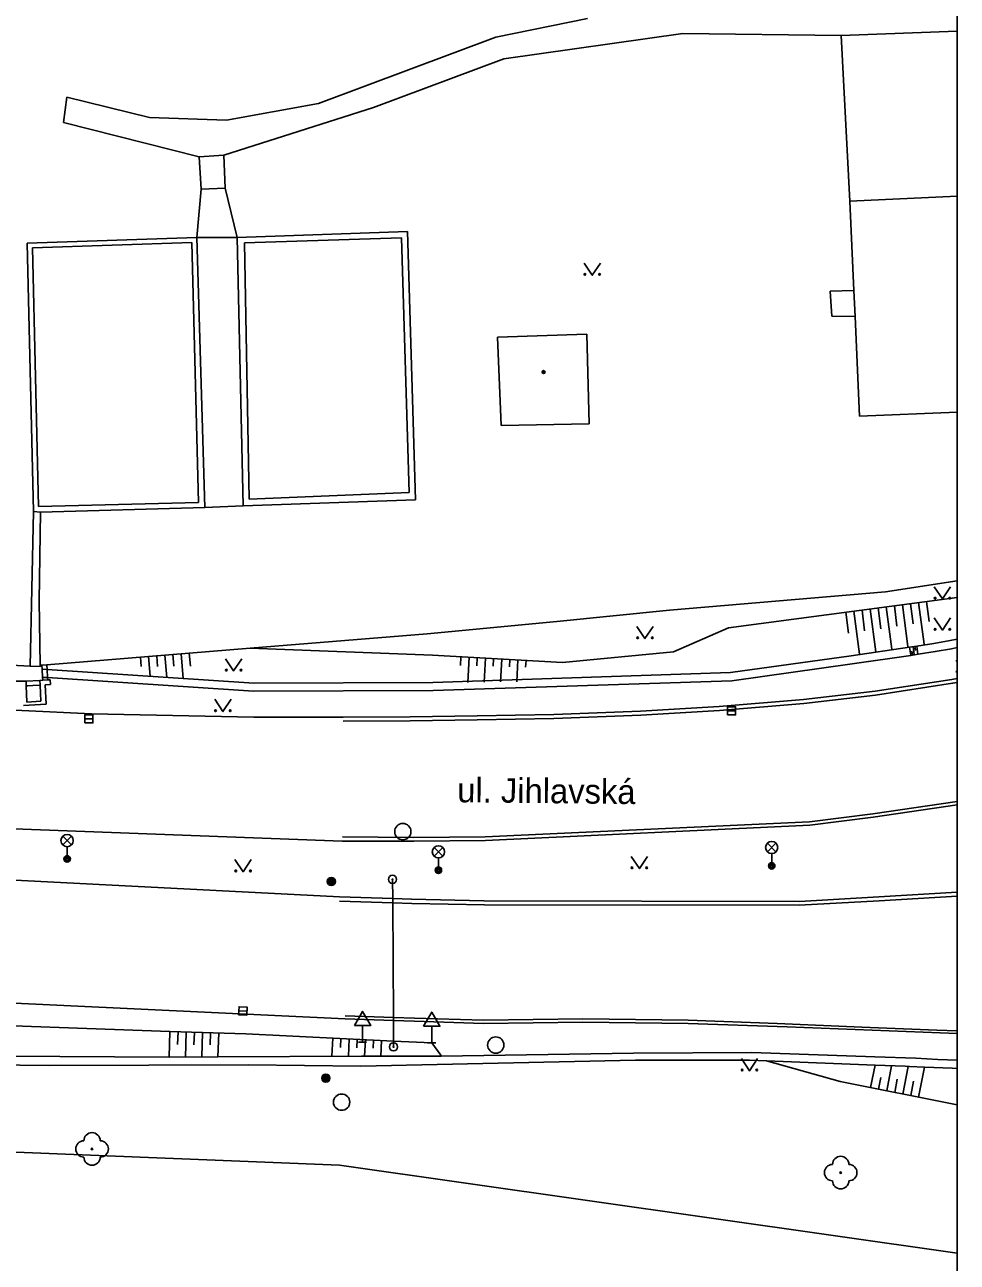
# Model space of a CAD drawing. Extents: x -599951 to -598963, y -1164095 to -1162939.
# Drawn here: x -599020.4 to -598963.2, y -1163192.8 to -1163116.9 of the extents above; entities that cross this region are included whole.
import ezdxf

# ---------------------------------------------------------------- set-up
doc = ezdxf.new("R2010")
doc.units = 0
for name, color, linetype in [('Level 10', 7, 'Continuous'), ('Level 11', 7, 'Continuous'), ('Level 14', 7, 'Continuous'), ('Level 15', 7, 'Continuous'), ('Level 22', 7, 'Continuous'), ('Level 25', 7, 'Continuous'), ('Level 27', 7, 'Continuous'), ('Level 33', 7, 'Continuous'), ('Level 34', 7, 'Continuous'), ('Level 36', 7, 'Continuous'), ('Level 39', 7, 'Continuous'), ('Level 49', 7, 'Continuous'), ('Level 5', 7, 'Continuous'), ('Level 52', 7, 'Continuous'), ('Level 54', 7, 'Continuous'), ('Level 7', 7, 'Continuous'), ('Vrstva 36', 7, 'Continuous'), ('Vrstva 53', 7, 'Continuous')]:
    doc.layers.add(name, color=color, linetype=linetype)

msp = doc.modelspace()

# ---------------------------------------------------------------- linework, layer by layer
at = {"layer": 'Level 10'}
for points in [[(-599000.85, -1163159.38), (-599006.33, -1163159.37), (-599016.28, -1163159.17), (-599020.56, -1163158.96), (-599040.32, -1163157.98), (-599052.62, -1163157.34), (-599061.75, -1163156.86), (-599083.57, -1163155.66), (-599106.72, -1163154.44)], [(-599000.91, -1163166.97), (-599023.78, -1163166.11), (-599041.12, -1163165.45), (-599081.82, -1163163.34), (-599159.19, -1163159.27), (-599169.17, -1163158.73), (-599204.95, -1163156.81)], [(-599000.85, -1163159.38), (-598996.75, -1163159.36), (-598992.65, -1163159.29), (-598987.95, -1163159.21), (-598982.63, -1163159.01), (-598977.8, -1163158.72), (-598972.63, -1163158.29), (-598968.25, -1163157.78), (-598963.54, -1163157.06), (-598963.215, -1163156.997)], [(-599205.09, -1163159.81), (-599169.37, -1163161.69), (-599159.51, -1163162.21), (-599109.74, -1163164.82), (-599081.83, -1163166.28), (-599044.34, -1163168.15), (-599041.81, -1163168.28), (-599023.78, -1163169.22), (-599001.08, -1163170.4)], [(-598963.215, -1163164.751), (-598968.36, -1163165.51), (-598972.25, -1163165.99), (-598992.14, -1163166.94)], [(-599000.91, -1163166.97), (-598996.53, -1163166.98), (-598992.14, -1163166.94)], [(-598972.88, -1163170.67), (-598968.02, -1163170.4), (-598963.215, -1163170.111)], [(-599001.08, -1163170.4), (-598997.82, -1163170.5)], [(-598997.82, -1163170.5), (-598996.66, -1163170.54), (-598992.24, -1163170.64)], [(-598992.24, -1163170.64), (-598972.88, -1163170.67)], [(-599049.76, -1163175.54), (-599041.81, -1163175.92), (-599026.19, -1163176.67), (-599000.74, -1163177.88)], [(-598997.78, -1163177.98), (-599000.74, -1163177.88)], [(-598963.215, -1163178.778), (-598973.64, -1163178.36), (-598979.71, -1163178.16), (-598986.17, -1163178.08), (-598992.25, -1163178.15), (-598996.5, -1163178.02), (-598997.78, -1163177.98)]]:
    msp.add_lwpolyline(points, dxfattribs=at)
at = {"layer": 'Level 11'}
for points in [[(-598969.72, -1163155.61), (-598966.15, -1163155.09), (-598965.7, -1163155.02), (-598964.64, -1163154.85), (-598963.65, -1163154.68), (-598963.215, -1163154.597)], [(-598977.11, -1163156.64), (-598969.72, -1163155.61)], [(-598969.65, -1163156.11), (-598966.07, -1163155.59), (-598965.62, -1163155.52), (-598964.56, -1163155.35), (-598963.56, -1163155.18), (-598963.215, -1163155.114)], [(-599019.31, -1163156.44), (-599019.32, -1163156.18)], [(-599019, -1163156.45), (-599019.31, -1163156.44)], [(-599019.28, -1163156.94), (-599019.31, -1163156.44)], [(-599019.02, -1163156.16), (-599019, -1163156.45)], [(-598995.37, -1163157.24), (-599006.34, -1163157.29), (-599019, -1163156.45)], [(-599019, -1163156.45), (-599018.98, -1163156.95)], [(-598977.04, -1163157.14), (-598969.65, -1163156.11)], [(-599020.91, -1163157.16), (-599020.29, -1163157.17)], [(-599020.29, -1163157.17), (-599019.45, -1163157.12)], [(-599020.29, -1163157.17), (-599020.28, -1163157.46)], [(-599019.45, -1163157.12), (-599019.27, -1163157.11)], [(-599019.43, -1163157.41), (-599019.45, -1163157.12)], [(-599018.98, -1163156.95), (-599019.28, -1163156.94)], [(-599019.27, -1163157.11), (-599019.28, -1163156.94)], [(-599019.27, -1163157.11), (-599018.97, -1163157.09)], [(-598995.34, -1163157.74), (-599006.36, -1163157.79), (-599018.98, -1163156.95)], [(-599018.98, -1163156.95), (-599018.97, -1163157.09)], [(-599018.97, -1163157.09), (-599018.81, -1163157.08)], [(-599018.81, -1163157.08), (-599018.79, -1163157.38)], [(-598995.37, -1163157.24), (-598977.11, -1163156.64)], [(-598995.34, -1163157.74), (-598977.04, -1163157.14)], [(-599020.28, -1163157.46), (-599020.18, -1163157.45)], [(-599020.28, -1163157.46), (-599020.24, -1163158.45)], [(-599020.18, -1163157.45), (-599019.88, -1163157.44)], [(-599019.88, -1163157.44), (-599019.43, -1163157.41)], [(-599019.38, -1163158.4), (-599019.43, -1163157.41)], [(-599018.79, -1163157.38), (-599019.13, -1163157.4)], [(-599019.13, -1163157.4), (-599019.07, -1163158.58)], [(-599000.85, -1163159.62), (-598996.75, -1163159.6), (-598992.65, -1163159.53), (-598987.94, -1163159.45), (-598982.62, -1163159.25), (-598977.78, -1163158.96), (-598972.61, -1163158.53), (-598968.22, -1163158.02), (-598963.5, -1163157.3), (-598963.215, -1163157.245)], [(-599019.07, -1163158.58), (-599020.46, -1163158.65)], [(-599020.24, -1163158.45), (-599019.38, -1163158.4)], [(-598963.215, -1163164.546), (-598968.39, -1163165.31), (-598972.27, -1163165.79), (-598992.15, -1163166.72)], [(-599000.9, -1163166.72), (-598996.53, -1163166.75), (-598992.15, -1163166.72)], [(-598997.82, -1163170.5), (-598997.83, -1163169.32)], [(-599001.09, -1163170.65), (-598997.82, -1163170.75)], [(-598997.82, -1163170.75), (-598997.82, -1163170.5)], [(-598997.82, -1163170.75), (-598996.64, -1163170.79), (-598992.19, -1163170.89)], [(-598997.78, -1163177.78), (-598997.82, -1163170.75)], [(-598972.9, -1163170.91), (-598968.01, -1163170.64), (-598963.215, -1163170.352)], [(-598992.19, -1163170.89), (-598972.9, -1163170.91)], [(-598997.78, -1163177.78), (-599000.73, -1163177.68)], [(-598963.215, -1163178.604), (-598964.47, -1163178.56), (-598969.06, -1163178.39), (-598974.26, -1163178.16), (-598979.7, -1163177.96), (-598986.17, -1163177.88), (-598992.25, -1163177.95), (-598996.49, -1163177.82), (-598997.78, -1163177.78)], [(-598997.78, -1163177.98), (-598997.78, -1163177.78)], [(-598997.77, -1163179.24), (-598997.78, -1163177.98)], [(-599052.11, -1163179.73), (-599045.47, -1163179.88), (-599040.32, -1163179.99), (-599031.67, -1163180.09), (-599011.53, -1163180.22), (-599008.53, -1163180.21), (-598999.74, -1163180.16), (-598994.84, -1163180.15)], [(-598997.77, -1163179.59), (-598997.77, -1163179.24)], [(-598994.84, -1163180.15), (-598983.05, -1163179.97), (-598975.81, -1163179.93), (-598968.26, -1163180.2)], [(-599052.14, -1163180.26), (-599031.55, -1163180.59), (-599018.85, -1163180.74), (-599006.69, -1163180.7), (-598999.78, -1163180.78), (-598982.94, -1163180.41), (-598975.94, -1163180.41), (-598974.91, -1163180.44)], [(-598974.91, -1163180.44), (-598968.25, -1163180.71)], [(-598968.26, -1163180.2), (-598965.76, -1163180.29), (-598964.41, -1163180.37), (-598963.215, -1163180.415)], [(-598968.25, -1163180.71), (-598966.4, -1163180.78), (-598966.15, -1163180.79), (-598965.22, -1163180.83), (-598963.53, -1163180.9), (-598963.215, -1163180.913)]]:
    msp.add_lwpolyline(points, dxfattribs=at)
at = {"layer": 'Level 14'}
for points in [[(-598963.215, -1163152.036), (-598977.23, -1163153.89), (-598980.6, -1163155.36), (-598987.41, -1163156.02), (-598995.39, -1163155.58), (-599006.56, -1163155.15)], [(-599040.24, -1163177.57), (-599032.58, -1163177.87), (-599026.19, -1163178.11), (-599011.48, -1163178.65), (-599006.83, -1163178.8), (-598997.77, -1163179.24)], [(-598997.77, -1163179.24), (-598995.43, -1163179.35), (-598994.87, -1163180.1)], [(-598994.87, -1163180.1), (-598994.84, -1163180.15)], [(-598974.91, -1163180.44), (-598970.39, -1163181.72), (-598963.215, -1163183.136)]]:
    msp.add_lwpolyline(points, dxfattribs=at)
at = {"layer": 'Level 15'}
for points in [[(-598967.57, -1163152.61), (-598967.22, -1163155.21)], [(-598967.07, -1163152.55), (-598966.91, -1163153.8)], [(-598966.58, -1163152.48), (-598966.24, -1163155.05)], [(-598966.08, -1163152.42), (-598965.92, -1163153.65)], [(-598965.59, -1163152.35), (-598965.25, -1163154.89)], [(-598965.09, -1163152.29), (-598964.93, -1163153.51)], [(-598970.05, -1163152.94), (-598969.88, -1163154.23)], [(-598969.55, -1163152.88), (-598969.2, -1163155.52)], [(-598969.05, -1163152.81), (-598968.89, -1163154.09)], [(-598968.56, -1163152.75), (-598968.21, -1163155.37)], [(-598968.06, -1163152.68), (-598967.9, -1163153.95)], [(-599013.28, -1163155.69), (-599013.23, -1163156.26)], [(-599012.78, -1163155.65), (-599012.68, -1163156.87)], [(-599012.28, -1163155.61), (-599012.23, -1163156.26)], [(-599011.78, -1163155.57), (-599011.67, -1163156.94)], [(-599011.29, -1163155.53), (-599011.23, -1163156.25)], [(-599010.79, -1163155.49), (-599010.66, -1163157)], [(-599010.29, -1163155.45), (-599010.22, -1163156.24)], [(-598993.64, -1163155.67), (-598993.67, -1163156.21)], [(-598993.14, -1163155.7), (-598993.22, -1163157.24)], [(-598966.15, -1163155.09), (-598966.07, -1163155.58)], [(-598965.96, -1163155.56), (-598966, -1163155.32)], [(-598965.92, -1163155.05), (-598965.85, -1163155.55)], [(-598965.81, -1163155.03), (-598965.78, -1163155.29)], [(-598965.7, -1163155.02), (-598965.63, -1163155.51)], [(-598992.64, -1163155.73), (-598992.67, -1163156.23)], [(-598992.14, -1163155.76), (-598992.22, -1163157.23)], [(-598991.64, -1163155.79), (-598991.67, -1163156.25)], [(-598991.14, -1163155.81), (-598991.22, -1163157.21)], [(-598990.64, -1163155.84), (-598990.67, -1163156.28)], [(-598990.14, -1163155.87), (-598990.22, -1163157.2)], [(-598989.64, -1163155.9), (-598989.67, -1163156.32)], [(-599011.48, -1163178.65), (-599011.53, -1163180.22)], [(-599010.98, -1163178.66), (-599011.01, -1163179.44)], [(-599010.48, -1163178.68), (-599010.53, -1163180.22)], [(-599009.98, -1163178.7), (-599010.01, -1163179.46)], [(-599009.48, -1163178.71), (-599009.53, -1163180.21)], [(-599008.98, -1163178.73), (-599009.01, -1163179.47)], [(-599008.48, -1163178.74), (-599008.53, -1163180.21)], [(-599001.49, -1163179.06), (-599001.55, -1163180.17)], [(-599000.99, -1163179.08), (-599001.02, -1163179.63)], [(-599000.49, -1163179.1), (-599000.54, -1163180.17)], [(-598999.99, -1163179.13), (-599000.02, -1163179.65)], [(-598999.49, -1163179.15), (-598999.54, -1163180.16)], [(-598998.99, -1163179.18), (-598999.02, -1163179.67)], [(-598998.5, -1163179.2), (-598998.54, -1163180.16)], [(-598968.53, -1163182.09), (-598968.25, -1163180.71)], [(-598967.54, -1163182.28), (-598967.24, -1163180.75)], [(-598968.04, -1163182.19), (-598967.89, -1163181.46)], [(-598966.56, -1163182.48), (-598966.23, -1163180.79)], [(-598965.58, -1163182.67), (-598965.22, -1163180.83)], [(-598967.05, -1163182.38), (-598966.89, -1163181.57)], [(-598966.07, -1163182.57), (-598965.9, -1163181.69)]]:
    msp.add_lwpolyline(points, dxfattribs=at)
at = {"layer": 'Level 22'}
for centre in [(-599016.25, -1163185.85), (-598970.36, -1163187.3)]:
    msp.add_circle(centre, 0.05, dxfattribs=at)
for centre, start, end in [((-599016.25, -1163185.35), 0, 180), ((-599016.75, -1163185.85), 90, 270), ((-599015.75, -1163185.85), 270, 90), ((-599016.25, -1163186.35), 180, 0), ((-598970.86, -1163187.3), 90, 270), ((-598970.36, -1163186.8), 0, 180), ((-598969.86, -1163187.3), 270, 90), ((-598970.36, -1163187.8), 180, 0)]:
    msp.add_arc(centre, 0.5, start, end, dxfattribs=at)
at = {"layer": 'Level 25'}
for centre, radius in [((-599001.58, -1163169.45), 0.25), ((-599001.58, -1163169.45), 0.2), ((-599001.58, -1163169.45), 0.15), ((-599001.58, -1163169.45), 0.1), ((-598997.83, -1163169.32), 0.25), ((-598997.83, -1163169.32), 0.0303), ((-599001.58, -1163169.45), 0.05), ((-598997.77, -1163179.59), 0.25), ((-598997.77, -1163179.59), 0.0303), ((-599001.92, -1163181.51), 0.25), ((-599001.92, -1163181.51), 0.2), ((-599001.92, -1163181.51), 0.15), ((-599001.92, -1163181.51), 0.1), ((-599001.92, -1163181.51), 0.05)]:
    msp.add_circle(centre, radius, dxfattribs=at)
at = {"layer": 'Level 27'}
for p, q in [((-599016.7, -1163159.48), (-599016.2, -1163159.48)), ((-598977.3, -1163158.99), (-598976.8, -1163158.99)), ((-599007.25, -1163177.375), (-599006.75, -1163177.405))]:
    msp.add_line(p, q, dxfattribs=at)
for points in [[(-598977.3, -1163159.24), (-598976.8, -1163159.24), (-598976.8, -1163158.74), (-598977.3, -1163158.74)], [(-599016.7, -1163159.73), (-599016.2, -1163159.73), (-599016.2, -1163159.23), (-599016.7, -1163159.23)], [(-599007.265, -1163177.624), (-599006.766, -1163177.655), (-599006.735, -1163177.156), (-599007.234, -1163177.125)]]:
    msp.add_lwpolyline(points, close=True, dxfattribs=at)
for centre in [(-598997.2, -1163166.39), (-598991.5, -1163179.48), (-599000.95, -1163182.98)]:
    msp.add_circle(centre, 0.5, dxfattribs=at)
at = {"layer": 'Level 33'}
for p, q in [((-599018.045, -1163167.21), (-599017.515, -1163166.68)), ((-599018.045, -1163166.68), (-599017.515, -1163167.21)), ((-599017.78, -1163167.32), (-599017.78, -1163168.07)), ((-598995.285, -1163167.9), (-598994.755, -1163167.37)), ((-598995.285, -1163167.37), (-598994.755, -1163167.9)), ((-598974.855, -1163167.63), (-598974.325, -1163167.1)), ((-598974.855, -1163167.1), (-598974.325, -1163167.63)), ((-598974.59, -1163167.74), (-598974.59, -1163168.49)), ((-598995.02, -1163168.01), (-598995.02, -1163168.76))]:
    msp.add_line(p, q, dxfattribs=at)
for centre, radius in [((-599017.78, -1163166.945), 0.375), ((-598974.59, -1163167.365), 0.375), ((-598995.02, -1163167.635), 0.375), ((-599017.78, -1163168.07), 0.2), ((-599017.78, -1163168.07), 0.145), ((-599017.78, -1163168.07), 0.0876), ((-598995.02, -1163168.76), 0.2), ((-598974.59, -1163168.49), 0.2), ((-598974.59, -1163168.49), 0.145), ((-598974.59, -1163168.49), 0.0876), ((-598995.02, -1163168.76), 0.145), ((-598995.02, -1163168.76), 0.0876)]:
    msp.add_circle(centre, radius, dxfattribs=at)
at = {"layer": 'Level 34'}
for p, q in [((-598999.67, -1163178.282), (-598999.67, -1163179.3)), ((-598995.43, -1163178.322), (-598995.43, -1163179.34)), ((-598999.92, -1163179.3), (-598999.42, -1163179.3)), ((-598995.68, -1163179.34), (-598995.18, -1163179.34))]:
    msp.add_line(p, q, dxfattribs=at)
for points in [[(-599000.17, -1163178.282), (-598999.17, -1163178.282), (-598999.67, -1163177.416)], [(-598995.93, -1163178.322), (-598994.93, -1163178.322), (-598995.43, -1163177.456)]]:
    msp.add_lwpolyline(points, close=True, dxfattribs=at)
at = {"layer": 'Level 36'}
msp.add_line((-598963.28, -1163155.89), (-598963.215, -1163155.988), dxfattribs=at)
for points in [[(-598986.09, -1163131.53), (-598985.59, -1163132.28), (-598985.09, -1163131.53)], [(-598964.62, -1163151.38), (-598964.12, -1163152.13), (-598963.62, -1163151.38)], [(-598964.62, -1163153.29), (-598964.12, -1163154.04), (-598963.62, -1163153.29)], [(-598982.86, -1163153.81), (-598982.36, -1163154.56), (-598981.86, -1163153.81)], [(-599008.07, -1163155.79), (-599007.57, -1163156.54), (-599007.07, -1163155.79)], [(-599008.73, -1163158.28), (-599008.23, -1163159.03), (-599007.73, -1163158.28)], [(-599007.49, -1163168.1), (-599006.99, -1163168.85), (-599006.49, -1163168.1)], [(-598983.2, -1163167.91), (-598982.7, -1163168.66), (-598982.2, -1163167.91)], [(-598976.45, -1163180.31), (-598975.95, -1163181.06), (-598975.45, -1163180.31)]]:
    msp.add_lwpolyline(points, dxfattribs=at)
for centre in [(-598986.04, -1163132.23), (-598985.141, -1163132.23), (-598964.57, -1163152.08), (-598963.671, -1163152.08), (-598964.57, -1163153.99), (-598963.671, -1163153.99), (-598982.81, -1163154.51), (-598981.911, -1163154.51), (-599008.02, -1163156.49), (-599007.121, -1163156.49), (-599008.68, -1163158.98), (-599007.781, -1163158.98), (-598983.15, -1163168.61), (-598982.251, -1163168.61), (-599007.44, -1163168.8), (-599006.541, -1163168.8), (-598976.4, -1163181.01), (-598975.501, -1163181.01)]:
    msp.add_circle(centre, 0.05, dxfattribs=at)
at = {"layer": 'Level 39'}
for radius in [0.09, 0.0398]:
    msp.add_circle((-598988.57, -1163138.22), radius, dxfattribs=at)
at = {"layer": 'Level 5'}
for p, q in [((-598969.8, -1163127.74), (-598963.215, -1163127.431)), ((-598969.21, -1163140.92), (-598963.215, -1163140.67))]:
    msp.add_line(p, q, dxfattribs=at)
for points in [[(-598969.56, -1163133.21), (-598969.8, -1163127.74)], [(-598969.48, -1163134.8), (-598969.56, -1163133.21)], [(-598969.21, -1163140.92), (-598969.48, -1163134.8)]]:
    msp.add_lwpolyline(points, dxfattribs=at)
at = {"layer": 'Level 52'}
for points in [[(-598991.4, -1163136.08), (-598985.93, -1163135.9)], [(-598985.93, -1163135.9), (-598985.78, -1163141.4)], [(-598991.18, -1163141.5), (-598991.4, -1163136.08)], [(-598985.78, -1163141.4), (-598991.18, -1163141.5)]]:
    msp.add_lwpolyline(points, dxfattribs=at)
at = {"layer": 'Level 54'}
msp.add_line((-598963.215, -1163117.315), (-598970.34, -1163117.58), dxfattribs=at)
for points in [[(-598991.49, -1163117.68), (-598985.87, -1163116.53)], [(-598999.53, -1163120.69), (-598991.49, -1163117.68)], [(-598991, -1163119.02), (-598980.04, -1163117.45)], [(-598980.04, -1163117.45), (-598970.34, -1163117.58)], [(-598970.34, -1163117.58), (-598969.8, -1163127.74)], [(-598998.99, -1163122), (-598991, -1163119.02)], [(-599002.37, -1163121.75), (-598999.53, -1163120.69)], [(-599018.01, -1163122.92), (-599017.79, -1163121.36)], [(-599017.79, -1163121.36), (-599012.72, -1163122.6)], [(-599008.17, -1163124.92), (-598998.99, -1163122)], [(-599008.01, -1163122.77), (-599002.37, -1163121.75)], [(-599018.01, -1163122.92), (-599009.69, -1163125.02)], [(-599012.72, -1163122.6), (-599008.01, -1163122.77)], [(-599009.69, -1163125.02), (-599008.17, -1163124.92)], [(-599009.69, -1163125.02), (-599009.57, -1163127)], [(-599008.1, -1163126.95), (-599008.17, -1163124.92)], [(-599009.57, -1163127), (-599009.82, -1163129.97)], [(-599008.1, -1163126.95), (-599009.57, -1163127)], [(-599007.35, -1163129.97), (-599008.1, -1163126.95)], [(-599007.35, -1163129.97), (-598996.91, -1163129.6)], [(-598996.91, -1163129.6), (-598996.42, -1163146.05)], [(-599020.23, -1163130.31), (-599009.82, -1163129.97)], [(-599019.84, -1163146.76), (-599020.23, -1163130.31)], [(-599019.9, -1163130.6), (-599010.14, -1163130.27)], [(-599019.54, -1163146.46), (-599019.9, -1163130.6)], [(-599010.14, -1163130.27), (-599009.72, -1163146.21)], [(-599009.82, -1163129.97), (-599009.33, -1163146.52)], [(-599009.82, -1163129.97), (-599007.35, -1163129.97)], [(-599006.98, -1163146.42), (-599007.35, -1163129.97)], [(-599006.91, -1163130.29), (-598997.28, -1163129.99)], [(-599006.61, -1163146), (-599006.91, -1163130.29)], [(-598997.28, -1163129.99), (-598996.81, -1163145.6)], [(-598971, -1163133.25), (-598969.56, -1163133.21)], [(-598970.9, -1163134.79), (-598971, -1163133.25)], [(-598969.48, -1163134.8), (-598970.9, -1163134.79)], [(-598996.81, -1163145.6), (-599006.61, -1163146)], [(-599009.72, -1163146.21), (-599019.54, -1163146.46)], [(-599009.33, -1163146.52), (-599019.42, -1163146.81)], [(-599006.98, -1163146.42), (-599009.33, -1163146.52)], [(-598996.42, -1163146.05), (-599006.98, -1163146.42)], [(-599020.05, -1163156.24), (-599019.84, -1163146.76)], [(-599019.42, -1163146.81), (-599019.84, -1163146.76)], [(-599019.49, -1163152.24), (-599019.42, -1163146.81)]]:
    msp.add_lwpolyline(points, dxfattribs=at)
at = {"layer": 'Level 7'}
msp.add_line((-598963.215, -1163151.019), (-598967.61, -1163151.7), dxfattribs=at)
for points in [[(-598967.61, -1163151.7), (-598980.86, -1163152.82), (-598987.75, -1163153.52), (-598995.71, -1163154.26), (-599006.56, -1163155.15)], [(-599019.49, -1163152.24), (-599019.44, -1163156.19)], [(-599020.05, -1163156.24), (-599039.4, -1163155.22), (-599052.41, -1163154.54)], [(-599006.56, -1163155.15), (-599019.02, -1163156.16)], [(-599019.44, -1163156.19), (-599019.44, -1163156.27), (-599020.05, -1163156.24)], [(-599019.32, -1163156.18), (-599019.44, -1163156.19)], [(-599019.02, -1163156.16), (-599019.32, -1163156.18)], [(-599053.8, -1163184.84), (-599042.55, -1163185.18), (-599041.29, -1163185.23), (-599001.09, -1163186.85), (-598963.215, -1163192.228)]]:
    msp.add_lwpolyline(points, dxfattribs=at)
at = {"layer": 'Vrstva 36'}
msp.add_line((-598963.215, -1163156.637), (-598963.215, -1163156.542), dxfattribs=at)
msp.add_arc((-598963.23, -1163156.59), 0.05, 72.30199, 287.69801, dxfattribs=at)
at = {"layer": 'Vrstva 53'}
msp.add_lwpolyline([(-599951.125, -1164094.695), (-598963.215, -1164094.695), (-598963.215, -1162939.4), (-599951.125, -1162939.4)], close=True, dxfattribs=at)

# ---------------------------------------------------------------- texts
at = {"layer": 'Level 49'}
msp.add_text('ul. Jihlavská', height=1.5, rotation=359.4, dxfattribs=at).set_placement((-598993.87, -1163164.59))

doc.saveas('drawing.dxf')
